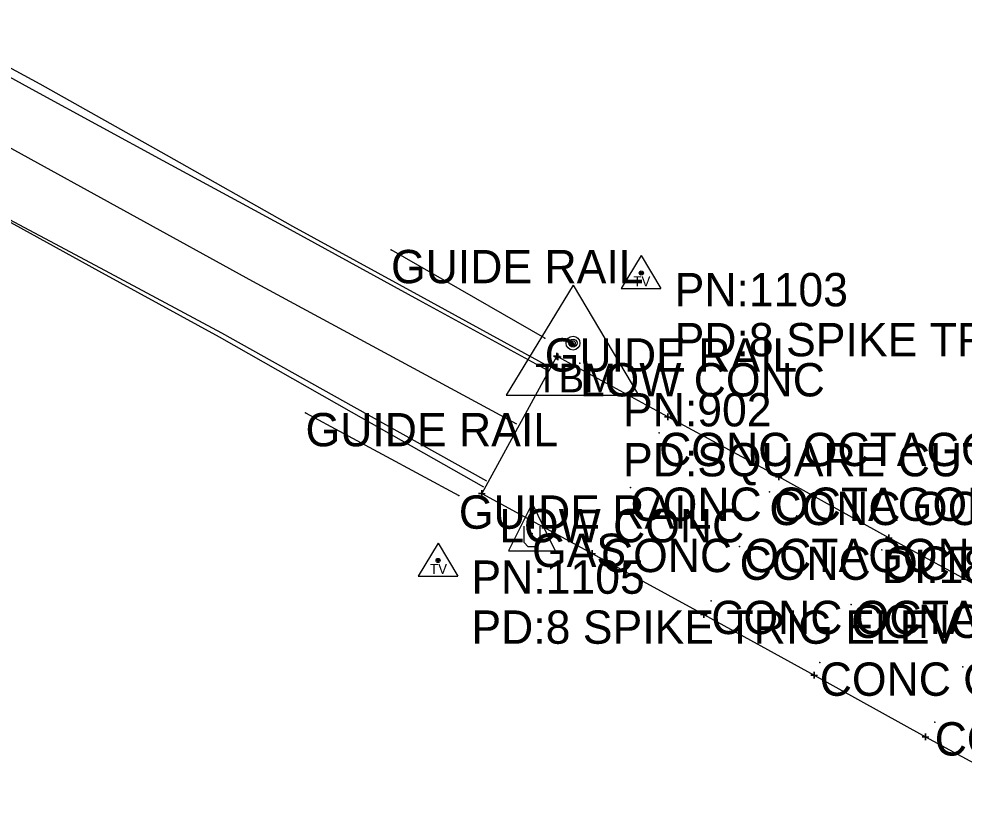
# Model space of a CAD drawing. Extents: x 1411444 to 1458157, y 300965 to 327300.
# Drawn here: x 1454655.1 to 1454797, y 302747.6 to 302864.4 of the extents above; entities that cross this region are included whole.
import ezdxf

# ---------------------------------------------------------------- set-up
doc = ezdxf.new("R2010")
doc.units = 0
for name, color, linetype in [('S_BRIDGE', 7, 'Continuous'), ('S_EDGE_PAVEMENT', 7, 'Continuous'), ('S_GUARDRAIL', 7, 'Continuous'), ('S_GUARDRAIL_ANNOT', 7, 'Continuous'), ('S_MISC_STRUCTURES_ANNOT', 7, 'Continuous'), ('S_MSC_PT_SYM', 7, 'Continuous'), ('S_PAVEMENT_CROWN', 7, 'Continuous'), ('S_PRIMARY_CTL', 7, 'Continuous'), ('S_PRIMARY_CTL_ANNOT', 7, 'Continuous'), ('S_RDW_PT_SYM', 7, 'Continuous'), ('S_SECONDARY_CTL', 7, 'Continuous'), ('S_SECONDARY_CTL_ANNOT', 7, 'Continuous'), ('S_SHOULDER', 7, 'Continuous'), ('S_STR_PT_SYM', 7, 'Continuous'), ('S_SURVEY_TEXT_ANNOT', 7, 'Continuous'), ('S_UTILITY_POLE', 7, 'Continuous'), ('S_UTILITY_POLE_ANNOT', 7, 'Continuous'), ('S_UTL_PT_SYM', 7, 'Continuous')]:
    doc.layers.add(name, color=color, linetype=linetype)

msp = doc.modelspace()

# ---------------------------------------------------------------- linework, layer by layer
at = {"layer": 'S_BRIDGE'}
for p, q in [((1454735.86, 302813.81), (1454724.63, 302793.19)), ((1454752.52, 302804.68), (1454736, 302813.69)), ((1454769.16, 302795.67), (1454752.52, 302804.68)), ((1454785.69, 302786.53), (1454769.16, 302795.67)), ((1454724.63, 302793.19), (1454741.19, 302784.18)), ((1454802.52, 302777.39), (1454785.69, 302786.53)), ((1454741.19, 302784.18), (1454757.91, 302775.03)), ((1454757.91, 302775.03), (1454774.46, 302765.94)), ((1454774.46, 302765.94), (1454791.19, 302756.67)), ((1454791.19, 302756.67), (1454807.79, 302747.62))]:
    msp.add_line(p, q, dxfattribs=at)
at = {"layer": 'S_EDGE_PAVEMENT'}
for points in [[(1454639.65, 302863.41), (1454657.61, 302853.56), (1454676.72, 302843.17), (1454695.83, 302832.79), (1454715.1, 302822.26), (1454734.37, 302811.73)], [(1454649.09, 302836.76), (1454667.31, 302827.02), (1454685.52, 302817.28), (1454705.41, 302806.19), (1454725.31, 302795.09)]]:
    msp.add_lwpolyline(points, dxfattribs=at)
at = {"layer": 'S_GUARDRAIL'}
for p, q in [((1454734.05, 302816.47), (1454710.98, 302829.73)), ((1454698.15, 302805.26), (1454721.16, 302792.89))]:
    msp.add_line(p, q, dxfattribs=at)
at = {"layer": 'S_MSC_PT_SYM'}
for points in [[(1454739.32, 302812.75), (1454739.32, 302812.8), (1454739.32, 302812.75), (1454739.27, 302812.75), (1454739.32, 302812.75), (1454739.32, 302812.7), (1454739.32, 302812.75), (1454739.37, 302812.75)], [(1454751.22, 302802.29), (1454751.22, 302802.34), (1454751.22, 302802.29), (1454751.17, 302802.29), (1454751.22, 302802.29), (1454751.22, 302802.24), (1454751.22, 302802.29), (1454751.27, 302802.29)], [(1454746.92, 302794.07), (1454746.92, 302794.12), (1454746.92, 302794.07), (1454746.87, 302794.07), (1454746.92, 302794.07), (1454746.92, 302794.02), (1454746.92, 302794.07), (1454746.97, 302794.07)], [(1454767.76, 302793.44), (1454767.76, 302793.49), (1454767.76, 302793.44), (1454767.71, 302793.44), (1454767.76, 302793.44), (1454767.76, 302793.39), (1454767.76, 302793.44), (1454767.81, 302793.44)], [(1454727.22, 302790.85), (1454727.22, 302790.9), (1454727.22, 302790.85), (1454727.17, 302790.85), (1454727.22, 302790.85), (1454727.22, 302790.8), (1454727.22, 302790.85), (1454727.27, 302790.85)], [(1454742.48, 302786.38), (1454742.48, 302786.43), (1454742.48, 302786.38), (1454742.43, 302786.38), (1454742.48, 302786.38), (1454742.48, 302786.33), (1454742.48, 302786.38), (1454742.53, 302786.38)], [(1454763.29, 302785.22), (1454763.29, 302785.27), (1454763.29, 302785.22), (1454763.24, 302785.22), (1454763.29, 302785.22), (1454763.29, 302785.17), (1454763.29, 302785.22), (1454763.34, 302785.22)], [(1454784.63, 302784.73), (1454784.63, 302784.78), (1454784.63, 302784.73), (1454784.58, 302784.73), (1454784.63, 302784.73), (1454784.63, 302784.68), (1454784.63, 302784.73), (1454784.68, 302784.73)], [(1454759.04, 302777.08), (1454759.04, 302777.13), (1454759.04, 302777.08), (1454758.99, 302777.08), (1454759.04, 302777.08), (1454759.04, 302777.03), (1454759.04, 302777.08), (1454759.09, 302777.08)], [(1454780.02, 302776.5), (1454780.02, 302776.55), (1454780.02, 302776.5), (1454779.97, 302776.5), (1454780.02, 302776.5), (1454780.02, 302776.45), (1454780.02, 302776.5), (1454780.07, 302776.5)], [(1454775.32, 302767.82), (1454775.32, 302767.87), (1454775.32, 302767.82), (1454775.27, 302767.82), (1454775.32, 302767.82), (1454775.32, 302767.77), (1454775.32, 302767.82), (1454775.37, 302767.82)], [(1454796.79, 302767.18), (1454796.79, 302767.23), (1454796.79, 302767.18), (1454796.74, 302767.18), (1454796.79, 302767.18), (1454796.79, 302767.13), (1454796.79, 302767.18), (1454796.84, 302767.18)], [(1454792.58, 302758.86), (1454792.58, 302758.91), (1454792.58, 302758.86), (1454792.53, 302758.86), (1454792.58, 302758.86), (1454792.58, 302758.81), (1454792.58, 302758.86), (1454792.63, 302758.86)]]:
    msp.add_lwpolyline(points, dxfattribs=at)
at = {"layer": 'S_PAVEMENT_CROWN'}
msp.add_lwpolyline([(1454653.49, 302845.26), (1454671.84, 302835.16), (1454690.2, 302825.05), (1454710, 302814.34), (1454729.8, 302803.63)], dxfattribs=at)
at = {"layer": 'S_PRIMARY_CTL'}
for p, q in [((1454738.29, 302824.45), (1454728.25, 302807.93)), ((1454738.29, 302824.45), (1454748.11, 302807.93)), ((1454728.25, 302807.93), (1454748.11, 302807.93))]:
    msp.add_line(p, q, dxfattribs=at)
for radius in [1.04, 0.609, 0.344]:
    msp.add_circle((1454738.29, 302815.75), radius, dxfattribs=at)
at = {"layer": 'S_RDW_PT_SYM'}
for points in [[(1454710.98, 302829.73), (1454710.98, 302829.78), (1454710.98, 302829.73), (1454710.93, 302829.73), (1454710.98, 302829.73), (1454710.98, 302829.68), (1454710.98, 302829.73), (1454711.03, 302829.73)], [(1454734.05, 302816.47), (1454734.05, 302816.52), (1454734.05, 302816.47), (1454734, 302816.47), (1454734.05, 302816.47), (1454734.05, 302816.42), (1454734.05, 302816.47), (1454734.1, 302816.47)], [(1454698.15, 302805.26), (1454698.15, 302805.31), (1454698.15, 302805.26), (1454698.1, 302805.26), (1454698.15, 302805.26), (1454698.15, 302805.21), (1454698.15, 302805.26), (1454698.2, 302805.26)], [(1454721.16, 302792.89), (1454721.16, 302792.94), (1454721.16, 302792.89), (1454721.11, 302792.89), (1454721.16, 302792.89), (1454721.16, 302792.84), (1454721.16, 302792.89), (1454721.21, 302792.89)]]:
    msp.add_lwpolyline(points, dxfattribs=at)
at = {"layer": 'S_SECONDARY_CTL'}
for p, q in [((1454748.54, 302828.88), (1454745.53, 302823.92)), ((1454748.54, 302828.88), (1454751.49, 302823.92)), ((1454745.53, 302823.92), (1454751.49, 302823.92)), ((1454718.04, 302785.74), (1454715.03, 302780.79)), ((1454718.04, 302785.74), (1454720.99, 302780.79)), ((1454715.03, 302780.79), (1454720.99, 302780.79))]:
    msp.add_line(p, q, dxfattribs=at)
for centre, radius in [((1454748.54, 302826.27), 0.311), ((1454748.54, 302826.27), 0.183), ((1454748.54, 302826.27), 0.103), ((1454718.04, 302783.13), 0.311), ((1454718.04, 302783.13), 0.183), ((1454718.04, 302783.13), 0.103)]:
    msp.add_circle(centre, radius, dxfattribs=at)
at = {"layer": 'S_SHOULDER'}
for points in [[(1454640.22, 302864.4), (1454658.26, 302854.67), (1454677.22, 302843.99), (1454696.19, 302833.31), (1454715.42, 302822.77), (1454734.65, 302812.22)], [(1454648.96, 302836.53), (1454667.08, 302826.6), (1454685.19, 302816.68), (1454705.01, 302805.42), (1454724.84, 302794.16)]]:
    msp.add_lwpolyline(points, dxfattribs=at)
at = {"layer": 'S_STR_PT_SYM'}
for points in [[(1454735.86, 302813.81), (1454735.86, 302814.31), (1454735.86, 302813.81), (1454735.36, 302813.81), (1454735.86, 302813.81), (1454735.86, 302813.31), (1454735.86, 302813.81), (1454736.36, 302813.81)], [(1454736, 302813.69), (1454736, 302814.19), (1454736, 302813.69), (1454735.5, 302813.69), (1454736, 302813.69), (1454736, 302813.19), (1454736, 302813.69), (1454736.5, 302813.69)], [(1454752.52, 302804.68), (1454752.52, 302805.18), (1454752.52, 302804.68), (1454752.02, 302804.68), (1454752.52, 302804.68), (1454752.52, 302804.18), (1454752.52, 302804.68), (1454753.02, 302804.68)], [(1454769.16, 302795.67), (1454769.16, 302796.17), (1454769.16, 302795.67), (1454768.66, 302795.67), (1454769.16, 302795.67), (1454769.16, 302795.17), (1454769.16, 302795.67), (1454769.66, 302795.67)], [(1454724.63, 302793.19), (1454724.63, 302793.69), (1454724.63, 302793.19), (1454724.13, 302793.19), (1454724.63, 302793.19), (1454724.63, 302792.69), (1454724.63, 302793.19), (1454725.13, 302793.19)], [(1454785.69, 302786.53), (1454785.69, 302787.03), (1454785.69, 302786.53), (1454785.19, 302786.53), (1454785.69, 302786.53), (1454785.69, 302786.03), (1454785.69, 302786.53), (1454786.19, 302786.53)], [(1454741.19, 302784.18), (1454741.19, 302784.68), (1454741.19, 302784.18), (1454740.69, 302784.18), (1454741.19, 302784.18), (1454741.19, 302783.68), (1454741.19, 302784.18), (1454741.69, 302784.18)], [(1454757.91, 302775.03), (1454757.91, 302775.53), (1454757.91, 302775.03), (1454757.41, 302775.03), (1454757.91, 302775.03), (1454757.91, 302774.53), (1454757.91, 302775.03), (1454758.41, 302775.03)], [(1454774.46, 302765.94), (1454774.46, 302766.44), (1454774.46, 302765.94), (1454773.96, 302765.94), (1454774.46, 302765.94), (1454774.46, 302765.44), (1454774.46, 302765.94), (1454774.96, 302765.94)], [(1454791.19, 302756.67), (1454791.19, 302757.17), (1454791.19, 302756.67), (1454790.69, 302756.67), (1454791.19, 302756.67), (1454791.19, 302756.17), (1454791.19, 302756.67), (1454791.69, 302756.67)]]:
    msp.add_lwpolyline(points, dxfattribs=at)
at = {"layer": 'S_UTILITY_POLE'}
for p, q in [((1454732.14, 302791.69), (1454728.61, 302784.6)), ((1454732.14, 302791.69), (1454735.62, 302784.6)), ((1454730.94, 302785.84), (1454730.94, 302788.28)), ((1454733.3, 302788.28), (1454733.3, 302785.84)), ((1454731.56, 302785.18), (1454730.94, 302785.84)), ((1454733.3, 302785.84), (1454732.76, 302785.18)), ((1454728.61, 302784.6), (1454735.62, 302784.6)), ((1454732.76, 302785.18), (1454731.56, 302785.18))]:
    msp.add_line(p, q, dxfattribs=at)
at = {"layer": 'S_UTL_PT_SYM'}
msp.add_lwpolyline([(1454732.14, 302787.16), (1454732.14, 302787.21), (1454732.14, 302787.16), (1454732.09, 302787.16), (1454732.14, 302787.16), (1454732.14, 302787.11), (1454732.14, 302787.16), (1454732.19, 302787.16)], dxfattribs=at)

# ---------------------------------------------------------------- texts
at = {"layer": 'S_GUARDRAIL_ANNOT'}
for p in [(1454710.98, 302824.73), (1454734.05, 302811.47), (1454698.15, 302800.26), (1454721.16, 302787.89)]:
    msp.add_text('GUIDE RAIL', height=5, dxfattribs=at).set_placement(p)
at = {"layer": 'S_MISC_STRUCTURES_ANNOT'}
for s, p in [('CONC OCTAGON COLLUMN DI:18IN', (1454751.22, 302797.29)), ('CONC OCTAGON COLLUMN DI:18IN', (1454746.92, 302789.07)), ('CONC OCTAGON COLLUMN DI:18IN', (1454767.76, 302788.44)), ('CONC OCTAGON COLLUMN DI:18IN', (1454742.48, 302781.38)), ('CONC OCTAGON COLLUMN DI:18IN', (1454763.29, 302780.22)), ('DI:18IN', (1454784.63, 302779.73)), ('CONC OCTAGON COLLUMN DI:18IN', (1454759.04, 302772.08)), ('CONC OCTAGON COLLUMN DI:18IN', (1454780.02, 302771.5)), ('CONC OCTAGON COLLUMN DI:18IN', (1454775.32, 302762.82)), ('CONC OCTAGON COLLUMN DI:18IN', (1454792.58, 302753.86))]:
    msp.add_text(s, height=5, dxfattribs=at).set_placement(p)
at = {"layer": 'S_PRIMARY_CTL'}
msp.add_text('TBM', height=4.287, rotation=360, dxfattribs=at).set_placement((1454732.63, 302808.36))
at = {"layer": 'S_PRIMARY_CTL_ANNOT'}
for s, p in [('PN:902', (1454745.79, 302803.25)), ('PD:SQUARE CUT ON NE CRNR BR', (1454745.79, 302795.75))]:
    msp.add_text(s, height=5, dxfattribs=at).set_placement(p)
at = {"layer": 'S_SECONDARY_CTL'}
for p in [(1454747.34, 302824.26), (1454716.83, 302781.12)]:
    msp.add_text('TV', height=1.5, rotation=360, dxfattribs=at).set_placement(p)
at = {"layer": 'S_SECONDARY_CTL_ANNOT'}
for s, p in [('PN:1103', (1454753.54, 302821.27)), ('PD:8 SPIKE TRIG ELEV', (1454753.54, 302813.77)), ('PN:1105', (1454723.04, 302778.13)), ('PD:8 SPIKE TRIG ELEV', (1454723.04, 302770.63))]:
    msp.add_text(s, height=5, dxfattribs=at).set_placement(p)
at = {"layer": 'S_SURVEY_TEXT_ANNOT'}
for p in [(1454739.32, 302807.75), (1454727.22, 302785.85)]:
    msp.add_text('LOW CONC', height=5, dxfattribs=at).set_placement(p)
at = {"layer": 'S_UTILITY_POLE_ANNOT'}
msp.add_text('GAS', height=5, dxfattribs=at).set_placement((1454732.14, 302782.16))

doc.saveas('drawing.dxf')
